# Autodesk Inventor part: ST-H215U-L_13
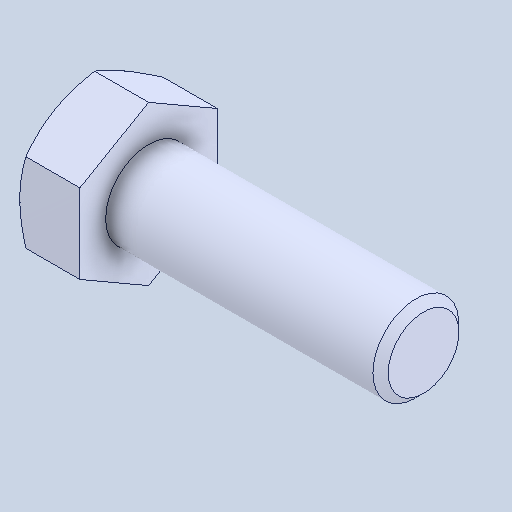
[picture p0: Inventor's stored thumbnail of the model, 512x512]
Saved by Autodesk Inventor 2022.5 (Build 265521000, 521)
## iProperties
Created: 2024-07
Part Number: ST-H215U-L_13
Material: 一般
Document SubType Name: Modeling
Designer: ImaoCorp
Density: 1 g/cm^3
Appearance: 既定
Author: ImaoCorp
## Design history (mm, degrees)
feature "ST-H215U-L_13"
node "ソリッド1"
